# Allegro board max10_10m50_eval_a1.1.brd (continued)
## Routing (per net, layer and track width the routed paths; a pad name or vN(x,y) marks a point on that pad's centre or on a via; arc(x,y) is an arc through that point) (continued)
3.3V_EN: length 15
  ART04 w0.406: v2(23.62,67.56) 25.78,67.56 26.04,67.31 26.04,66.55 25.53,66.04 25.53,65.53 26.29,64.77 v2(26.29,64.01)
  BOTTOM w0.305: v2(23.62,67.56) 24.13,67.56 25.81,69.24 U17.18
  BOTTOM w0.406: v2(26.29,64.01) 26.29,64.77 26.8,65.28 C207.1 R284.2 R280.1 R279.1
3.3V_OV5640: length 1.3
  TOP w0.254: J3.16 55.19,12.26
  vias: v4(55.75,13.34) v4(55.75,12.45) v4(56.64,13.34) v4(56.64,12.45)
3.3V_POK: length 23.4
  TOP w0.147: v2(25.4,66.8) 25.4,66.29 25.15,66.04 25.15,64.39 26.67,62.86 28.24,62.86 28.38,62.72 R281.1 v2(29.34,62.23)
  BOTTOM w0.147: R282.2 33.59,55.56 34.29,56.26 34.29,61.09 33.66,61.72 29.84,61.72 v2(29.34,62.23) ; v2(25.4,66.8) 25.4,68.07 25.92,68.59 U17.17
3.3V_SI510: length 14.4
  ART04 w0.406: v2(35.56,56.13) 37.21,54.48 39.12,54.48 40.89,56.26 v2(44.2,56.26)
  BOTTOM w0.406: R214.1 35.43,56.26 v2(35.56,56.13) ; U15.6 41.79,55.56 C240.1 L9.2 v2(44.2,56.26)
3.3V_SI5338: length 5
  BOTTOM w0.254: U14.16 19.44,52.58 v2(19.18,52.32) ; U14.11 22.34,54.49 v2(22.48,54.36) ; v2(22.48,56.64) 22.33,56.49 U14.7 ; v2(20.19,52.32) 19.93,52.58 U14.15 ; U14.24 16.87,56.49 v2(16.76,56.39)
3.3V_VFB: length 4.9
  BOTTOM w0.305: R229.2 30.42,66.87 30.23,67.06 29.08,67.06 28.9,67.24 U17.14
  BOTTOM w0.406: R223.1 C91.2 R229.2
5V: length 21.7
  TOP w0.254: v2(86.61,60.58) 86.42,60.77 J4.18
  TOP w0.406: D2.8 74.97,65.06 v2(74.8,64.9) ; D1.8 74.88,60.62 v2(74.72,60.45)
  ART04 w0.617: J11.2 18.25,36.2 ; J11.2 17.14,37.3 ; J11.2 16.04,36.2 ; J11.2 17.14,35.09
  BOTTOM w0.406: v2(86.61,62.48) R115.2 R114.2 ; R280.2 28.13,61.4 ; R199.1 22.67,25.59 23.11,26.03 v4(23.11,28.32) ; C43.1 75.5,64.9 v2(74.8,64.9) ; C42.1 75.5,60.45 v2(74.72,60.45)
  BOTTOM w0.655: 16.14,36.2 J11.2 ; J11.2 17.14,37.2 ; J11.2 18.15,36.2
  vias: v4(16.64,37.72) v4(17.4,37.72) v4(20.19,74.17) v4(20.19,73.41) v4(21.08,74.17) v4(21.08,73.41) v4(21.97,74.17) v4(21.97,73.41) v4(23.11,30.1) v4(23.11,29.21) v4(23.88,30.1) v4(23.88,29.21) v4(23.88,28.32) v4(26.29,61.34) v4(26.29,60.58) v4(27.05,61.34) v4(27.05,60.58) v4(27.81,61.34) v4(27.81,60.58) v4(50.29,61.59) v4(50.29,60.71) v4(51.18,61.59) v4(51.18,60.71) v4(52.07,61.59) v4(52.07,60.71) v4(90.17,60.83) v4(90.17,59.94) v4(90.93,60.83) v4(90.93,59.94) v4(91.69,60.83) v4(91.69,59.94)
5V_DCIN: length 31.6
  TOP w0.254: V1.2 14.86,16.13 14.68,16.31 12.88,16.31 12.7,16.13 R222.2
  TOP w0.305: U18.2 25.53,15.56 25.65,15.68 R224.2
  TOP w0.406: R224.2 26.67,15.1 25.54,13.97 16.13,13.97 15.49,14.61 13.84,14.61
  TOP w0.508: R217.1 10.79,19.43 10.29,18.92 10.29,18.29
  TOP w0.762: J10.2 7.2,15.24 ; J10.2 9.26,15.24 ; J10.2 8.23,17.7 ; J10.2 8.23,12.78
5V_FB: length 3.4
  TOP w0.305: v2(20.57,17.27) 20.38,17.46 U18.12
  BOTTOM w0.406: R233.2 R226.1 v2(20.57,17.27)
5V_GATE: length 3.6
  TOP w0.254: U18.9 17.34,19.37 17.02,19.69 R225.2 R231.2
5V_IMON: length 2.5
  TOP w0.305: v2(17.27,16.76) 17.34,16.83 U18.13
  BOTTOM w0.406: R232.2 17.21,16.83 v2(17.27,16.76)
5V_LED_R: length 2
  TOP w0.406: v2(21.08,24.51) 21.26,24.33 D9.1
  BOTTOM w0.406: R199.2 v2(21.08,24.51)
5V_MONITOR: length 6.3
  TOP w0.305: 25.78,20.45 25.78,19.94 25.21,19.37 U18.8
  TOP w0.655: J11.1 20.69,36.2 ; J11.1 19.68,35.19 ; J11.1 19.68,37.2 ; J11.1 18.68,36.2
  vias: v4(21.84,21.97) v4(21.84,21.21) v4(22.61,21.97) v4(22.61,21.21) v4(23.37,21.97) v4(23.37,21.21) v4(24.13,21.97) v4(24.13,21.21)
5V_N: length 3.4
  TOP w0.254: V2.1 17.46,15.56 U18.15
5V_OV: length 3.6
  TOP w0.305: U18.4 25.91,16.83 26.16,16.57 R224.1
  TOP w0.406: R230.2 R224.1
5V_P: length 3.4
  TOP w0.254: V1.1 17.34,14.92 U18.16
5V_PG: length 2.8
  TOP w0.305: v2(17.27,18.54) 17.46,18.73 U18.10
  BOTTOM w0.406: R227.1 17.84,18.67 17.72,18.54 v2(17.27,18.54)
5V_R1.2CORE: length 17.8
  TOP w0.305: U21.16 18.12,25.52 18.35,25.29 C120.1
  TOP w0.406: C120.1 19.68,24.51 v2(20.45,25.27) 22.35,27.18 22.35,29.97 22.03,30.29 C111.1
  ART04 w0.508: v2(15.11,26.16) 15.37,25.91 19.81,25.91 v2(20.45,25.27)
  BOTTOM w0.406: v4(21.59,28.32) 21.91,28 R252.2
  vias: v4(20.07,29.21) v4(20.07,28.32) v4(20.83,29.21) v4(20.83,28.32) v4(21.59,29.21)
5V_R1.2VCCIO: length 6.6
  BOTTOM w0.203: U22.11 88.03,54.2 87.88,54.35 ; 88.43,53.59 U22.12
  BOTTOM w0.406: 87.88,54.35 87.69,54.54 C210.2 90.3,55.12 90.68,54.74 v4(90.68,54.36)
  vias: v4(89.15,54.36) v4(89.15,53.59) v4(89.92,54.36) v4(89.92,53.59) v4(90.68,53.59)
5V_R1.8: length 11.7
  TOP w0.406: v2(50.8,64.01) 50.8,64.64 51.05,64.9 R257.1
  BOTTOM w0.203: 53.34,62.74 53.98,62.74 54.23,62.99 54.23,63.75 54.17,63.81 U20.11 ; 53.34,61.98 54.36,61.98 54.97,62.59 U20.9 ; 52.83,63.63 53.21,63.63 53.38,63.79 U20.13 ; 53.34,62.36 54.1,62.36 54.57,62.83 U20.10
5V_R2.5: length 4.5
  TOP w0.203: C212.2 31.67,57.98 31.62,57.93 U19.11 ; U19.12 31.41,58.33
  TOP w0.406: v4(33.27,59.44) 32.89,59.05 32.89,58.17 32.7,57.98 C212.2
  vias: v4(31.75,60.32) v4(31.75,59.44) v4(32.51,60.32) v4(32.51,59.44) v4(33.27,60.32)
5V_R3.3: length 15.7
  ART04 w0.508: v4(26.29,65.79) 27.56,67.06 30.23,67.06 v4(30.99,67.82)
  BOTTOM w0.305: C96.1 27.24,66.8 27.6,67.16 U17.16
  BOTTOM w0.508: C96.1 26.8,66.29 v4(26.29,65.79) 25.65,65.15 23.24,65.15 22.86,65.53 22.86,68.96
5V_UV: length 21.4
  TOP w0.305: U18.3 22.54,16.19 v2(22.35,16.38) 20.64,18.1 U18.11
  BOTTOM w0.508: v2(22.35,16.38) 22.35,16 21.97,15.62 16.26,15.62 15.11,16.76 15.11,21.72 14.16,22.67 R264.2
GND: length 750.1
  TOP w0.152: U4.N3 U4.M4 ; U4.H18 U4.J17 ; U4.C8 U4.D9 ; U4.V13 U4.U12
  TOP w0.203: v2(28.19,56.26) 28.66,56.73 U19.5 ; v3(29.72,57.78) 29.57,57.93 U19.2 28.05,57.93 v2(27.81,58.17)
  TOP w0.254: J3.7 v2(50.68,12.31) ; v2(52.2,12.32) 52.19,12.31 J3.10 ; J3.3 48.68,12.11 v2(48.9,12.32) 49.19,12.03 J3.4
  TOP w0.305: J4.8 v2(86.69,65.77) ; U2.F5 v3(81.28,44.18) ; U4.U12 32.5,42.98 v3(32.77,43.24) ; U4.N18 U4.M18 U4.M17 34.49,44.97 33.91,44.39 v3(33.91,44.26) ; U4.H3 U4.J3 U4.J4 29.61,46.47 v3(30.11,45.97) ; U2.H2 v3(78.68,42.23) U2.J1 ; U18.7 22.42,18.73 v2(22.23,18.54) ; U4.D9 31,48.53 v3(30.48,48.01) ; v3(83.88,37.69) 83.64,37.92 U2.R9 ; v3(29.46,44.58) 29.07,44.97 U4.M4 ; J4.17 86.29,61.27 v2(86.61,61.59) ; J4.2 v2(86.69,68.77) ; U2.C2 v3(78.68,46.13) ; v3(84.8,40.61) U2.L10 ; C120.2 17.47,24.52 U21.15 ; U2.P1 v3(77.85,38.66) ; U2.N10 v3(84.8,39.31) ; U2.C6 v3(81.93,46.13) ; U2.P10 v3(84.8,38.66) ; U4.V8 U4.V9 U4.U9 31,42.85 v3(30.61,43.24) ; v3(32.89,48.07) 32.5,48.46 U4.D12 U4.C12 U4.C13 ; U2.M5 v3(80.63,39.64) ; U2.J8 v3(83.23,42.23) ; U2.E10 v3(83.88,44.18) ; U2.D10 v3(84.53,45.48) ; v3(78.03,45.48) U2.D1 ; J4.5 v2(86.69,67.27) ; U2.R6 v3(81.93,37.69) ; U2.R5 v3(80.63,37.69) ; v3(33.15,46.74) 34.04,46.74 v3(34.29,46.48) 34.3,46.47 U4.J17 ; U2.J5 v3(81.28,42.23) ; J4.11 v2(86.69,64.27) ; U2.G10 v3(83.88,42.88) ; U2.E1 v3(77.78,44.51) ; U2.C5 v3(81.28,46.13) ; U2.C9 v3(83.88,46.13) ; U2.N1 v3(77.85,39.31) ; U2.R2 v3(78.68,37.69)
  TOP w0.381: U1.E20 65.51,43.47 v1(65.51,43.46) ; U1.E20 64.52,43.47 v1(64.51,43.47) ; U1.E20 64.52,44.46 v1(64.52,44.47) ; U1.AA4 v1(48.51,28.46) ; v1(65.52,40.47) U1.J20 64.78,40.2 64.25,40.2 U1.J19 ; U1.T16 v1(61.52,32.46) ; U1.N4 v1(48.51,35.46) U1.P3 ; U1.P17 v1(62.52,35.47) ; U1.V6 v1(50.51,30.46) ; U1.M7 v1(51.51,36.46) ; U1.E17 62.51,43.47 v1(62.52,43.47) ; v1(50.51,43.47) U1.F6 ; U1.F6 50.52,42.47 v1(50.51,42.47) ; U1.F6 v1(51.51,43.47) ; U1.F20 65.51,42.47 v1(65.51,42.46) ; U1.F20 v1(64.51,42.46) ; U1.F20 v1(64.51,43.47) ; U1.F20 v1(65.51,43.46) ; U1.R19 v1(64.52,33.46) ; U1.D19 64.51,44.47 v1(64.52,44.47) ; U1.B21 v1(65.52,46.47) ; U1.B21 v1(66.52,47.47) ; U1.B21 65.52,47.46 v1(65.52,47.47) U1.B20 65.51,46.47 v1(65.52,46.47) ; v1(65.52,46.47) U1.C20 65.51,45.47 v1(65.51,45.46) ; U1.P2 47.02,34.96 v1(47.52,35.46) ; v1(65.51,43.46) 65.52,43.46 U1.F21 v1(65.51,42.46) ; U1.F19 64.51,43.46 v1(64.51,43.47) ; U1.F19 63.52,42.47 v1(63.51,42.47) ; U1.F19 64.51,42.47 v1(64.51,42.46) ; U1.Y12 v1(57.52,29.46) ; U1.V19 v1(63.52,30.46) ; U1.M22 v1(67.52,36.46) ; R20.1 v2(73.22,34.67) ; U1.E5 v1(49.51,44.47) ; U1.V2 v1(47.52,30.46) ; U1.N21 v1(66.52,36.46) U1.M21 ; U1.M16 v1(61.52,36.46) ; v1(64.52,44.47) U1.E19 v1(64.51,43.47) ; v1(64.52,44.47) U1.D20 v1(65.51,45.46) ; U1.D4 v1(48.51,45.47) ; U1.L13 v1(58.52,38.47) ; U1.L21 v1(66.52,38.47) ; v1(62.52,43.47) 62.52,43.46 U1.F18 ; v1(62.52,43.47) U1.F17 62.51,42.47 v1(62.52,42.47) ; U1.B13 v1(58.52,47.47) ; v1(65.51,45.46) U1.C21 v1(66.52,46.47) ; U1.B18 v1(63.52,47.47) ; U1.R22 v1(66.51,33.46) ; U1.B6 v1(50.51,47.47) ; U1.Y15 v1(59.51,29.47) ; v1(64.51,42.46) U1.G19 v1(63.51,42.47) ; v1(64.51,42.46) 64.52,42.46 U1.G20 ; U1.R3 v1(47.51,34.46) ; U1.G15 v1(60.52,42.47) ; U1.T4 v1(49.52,33.47) ; U1.U21 66.51,31.47 v1(66.52,31.47) ; v1(46.51,27.46) 46.01,26.97 U1.AB1 ; U1.V20 v1(65.52,30.46) ; v1(50.51,42.47) U1.G6 ; v1(50.51,42.47) U1.G5 ; U1.J16 v1(61.52,40.47) U1.H17 ; U1.D16 v1(61.52,45.47) ; U1.L22 v1(67.52,38.47) ; U1.AA18 v1(63.52,27.46) ; v1(65.51,42.46) 65.52,42.46 U1.G21 ; v1(62.52,42.47) U1.G17 ; v1(62.52,42.47) U1.F18 ; v1(62.52,42.47) 62.52,42.46 U1.G18 63.51,42.46 v1(63.51,42.47) ; U1.U13 v1(58.52,31.46) ; U1.W21 v1(65.52,29.46) ; U1.B9 v1(54.51,47.47) ; v1(67.52,31.47) 67.51,31.47 U1.U22 ; U1.F18 v1(63.51,42.47) ; U1.N13 v1(58.52,36.47) ; U1.V18 v1(62.51,31.47) ; U1.N15 v1(59.52,35.46) ; U1.T20 v1(65.52,32.46) ; U1.P6 v1(50.51,34.46) ; v1(50.51,32.46) 50.32,32.66 U1.T5 ; U1.T8 v1(52.51,33.46) ; U1.L17 v1(62.52,38.47) ; U1.P18 v1(63.52,34.46) ; U1.AB22 v1(66.51,27.47) ; U1.A1 v1(45.51,48.47) ; U1.A22 v1(67.52,48.47) ; U1.K12 v1(57.52,39.47) ; U1.F13 v1(58.52,43.47) ; U1.P19 v1(64.52,34.46) ; U1.N11 v1(55.51,35.46) ; U1.F10 v1(54.51,43.47) ; U1.E6 v1(50.51,44.47) ; U1.D11 v1(56.52,44.46) ; U1.T14 v1(59.51,32.47) ; C251.2 25.27,58.17 ; U1.Y9 v1(53.51,28.46) ; U1.M10 v1(54.51,36.46) ; v1(51.52,32.46) U1.T6 ; U1.P20 v1(65.52,34.46) ; U1.L19 v1(64.52,38.47) ; U1.E7 v1(51.51,44.47) ; U1.U10 v1(54.51,31.46) ; U1.M8 v1(52.51,36.46) ; U1.R21 v1(66.52,34.47) ; U1.M19 v1(64.52,36.46) ; U1.E2 v1(46.51,43.47)
  TOP w0.406: R144.1 41.34,45.85 41.4,45.91 C71.2 43.37,45.91 v2(43.43,45.97) ; 85.22,29.84 SW1.3 82.68,29.84 ; D9.2 19.05,23.24 18.92,23.37 v2(18.54,23.37) v2(17.78,23.37) v2(17.02,23.37) ; v1(39.62,36.45) 39.31,36.77 C122.2 ; 82.68,31.12 SW1.2 85.22,31.12 ; U1.J2 v1(47.51,39.47) ; v1(57.53,22.87) 57.48,22.92 C37.2 ; v2(73,14.63) S3.2 v2(69.87,14.63) S4.1 ; C120.2 v2(16.51,24.51) R243.1 ; v2(17.27,17.65) 17.02,17.91 C98.1 ; U1.K4 v1(48.52,39.47) ; U1.K5 v1(49.52,39.47) ; D2.7 76.4,65.71 v2(76.83,65.28) ; U1.J8 53.51,39.47 ; 53.51,39.47 U1.J9 v1(54.51,39.47) U1.K10 ; 53.51,39.47 v1(53.52,39.46) ; C212.1 32.96,57.09 v2(33.53,56.52) 33.53,55.75 33.2,55.42 D10.2 ; R230.1 27.69,15.11 v2(27.3,14.73) ; D1.7 74.87,61.27 v2(74.68,61.47) ; U1.K6 v1(50.52,39.47) U1.J6 v1(50.51,40.47) U1.H5 v1(49.51,40.47) U1.J5 ; U1.G8 v1(52.51,42.47) ; 85.22,28.58 SW1.4 v2(82.68,28.58) ; 85.22,32.38 SW1.1 82.68,32.38 ; C99.2 C97.2 28.32,17.65 v2(28.45,17.53) ; v1(70.74,29.59) 70.68,29.65 C31.2 ; U1.L5 v1(49.51,38.47) ; v1(78.74,33.02) 79.06,33.34 R180.1 ; 16.76,55.37 16.32,55.37 C88.2 ; R286.1 85.22,52.96 v2(85.09,53.09) ; v2(50.29,54.86) 50.29,54.61 v2(50.8,54.1) 50.86,54.04 C170.2 C169.1 ; U1.H11 v1(55.51,41.47) ; U1.K3 v1(47.51,38.47) ; S3.1 v2(76.83,14.63)
  TOP w0.508: SW2.4 39.5,55.24 ; C63.2 15.18,40.2 v2(15.24,40.26) ; SW2.2 39.5,57.78 ; SW2.1 39.5,59.05 ; J7.10 v2(10.16,46.35) ; SW2.3 39.5,56.52
  TOP w0.61: 61.34,6.44 J12.20 ; J12.20 62.52,7.62 ; J12.20 60.16,7.62 ; J12.20 61.34,8.8 ; 7,23.37 SW3.1 ; SW3.1 8,22.36 ; SW3.1 9,23.37 ; SW3.1 8,24.37 ; 1.91,27.44 SW3.6 ; SW3.6 1.91,29.45 ; SW3.6 2.91,28.45 ; 68.96,8.98 J12.13 ; J12.13 70.14,10.16 ; J12.13 68.96,11.34 ; J12.13 67.78,10.16 ; J4.G2 87.49,72.02 ; J4.G2 83.43,72.02 ; J4.G2 85.46,70.88 ; J4.G2 85.46,73.16 ; 60.16,10.16 J12.19 ; J12.19 61.34,8.98 ; J12.19 62.52,10.16 ; J12.19 61.34,11.34 ; 76.58,8.98 J12.7 ; J12.7 75.4,10.16 ; J12.7 77.76,10.16 ; J12.7 76.58,11.34 ; J12.8 77.76,7.62 ; J12.8 76.58,8.8 ; J12.8 76.58,6.44 ; J12.8 75.4,7.62 ; J12.14 70.14,7.62 ; J12.14 68.96,6.44 ; J12.14 67.78,7.62 ; J12.14 68.96,8.8 ; 85.46,56.38 J4.G4 ; J4.G4 83.43,57.52 ; J4.G4 85.46,58.66 ; J10.3 5.03,11.62 ; J10.3 5.03,9.46 ; J10.3 2.52,10.54 ; J10.3 7.55,10.54 ; J4.G1 91.43,73.16 ; J4.G1 89.68,72.02 ; J4.G1 91.43,70.88 ; J9.11 22.53,66.42 ; J9.11 20.65,66.42 ; J9.11 21.59,65.48 ; J5.5 8.46,34.6 ; J9.5 21.59,64.82 ; J9.5 21.59,62.94 ; J9.5 20.65,63.88 ; J9.5 22.53,63.88 ; J10.1 3.11,15.24 ; J10.1 2.03,17.75 ; J10.1 2.03,12.73
  GND02 w0.406: J14.12 72.06,73.66 ; J14.12 71.12,74.6 ; J14.12 70.18,73.66 ; J14.12 71.12,72.72 ; 2.03,12.93 J10.1 ; J10.1 2.91,15.24 ; J10.1 2.03,17.55 ; 75.7,10.16 J12.7 ; J12.7 77.46,10.16 ; J12.7 76.58,9.28 ; J12.7 76.58,11.04 ; J4.G2 87.29,72.02 ; J4.G2 85.46,71.08 ; J4.G2 83.63,72.02 ; J4.G2 85.46,72.96 ; J10.3 7.34,10.54 ; J10.3 2.72,10.54 ; J10.3 5.03,9.66 ; J10.3 5.03,11.42 ; J4.G4 85.46,58.46 ; J4.G4 83.63,57.52 ; J4.G4 85.46,56.58 ; J4.G4 87.29,57.52 ; 91.43,56.58 J4.G3 ; J4.G3 91.43,58.46 ; J4.G3 89.88,57.52 ; SW3.6 1.91,29.25 ; SW3.6 2.71,28.45 ; SW3.6 1.91,27.65 ; 75.7,7.62 J12.8 ; J12.8 76.58,6.74 ; J12.8 77.46,7.62 ; J12.8 76.58,8.5 ; 7.2,23.37 SW3.1 ; SW3.1 8,22.57 ; SW3.1 8,24.17 ; SW3.1 8.8,23.37 ; J8.11 44.45,67.36 ; J8.11 44.45,65.48 ; J8.11 43.51,66.42 ; J8.11 45.39,66.42 ; 8.19,34.6 J5.5 7.5,35.28 ; J13.14 26.29,8.5 ; J13.14 25.41,7.62 ; J13.14 27.17,7.62 ; J13.14 26.29,6.74 ; J12.19 62.22,10.16 ; J12.19 61.34,11.04 ; J12.19 61.34,9.28 ; J12.19 60.46,10.16 ; 18.67,7.62 18.67,8.5 ; 18.67,7.62 17.79,7.62 ; 18.67,7.62 18.67,6.74 ; 18.67,7.62 19.55,7.62 ; 25.41,10.16 J13.13 ; J13.13 27.17,10.16 ; J13.13 26.29,9.28 ; J13.13 26.29,11.04 ; J9.11 21.59,67.36 ; J9.11 21.59,65.48 ; J9.11 20.65,66.42 ; J9.11 22.53,66.42 ; J8.5 44.45,64.82 ; J8.5 44.45,62.94 ; J8.5 45.39,63.88 ; J8.5 43.51,63.88 ; J9.5 21.59,64.82 ; J9.5 21.59,62.94 ; J9.5 20.65,63.88 ; J9.5 22.53,63.88 ; 70.18,71.12 J14.11 ; J14.11 71.12,72.06 ; J14.11 72.06,71.12 ; J14.11 71.12,70.18 ; 61.34,6.74 J12.20 ; J12.20 61.34,8.5 ; J12.20 60.46,7.62 ; J12.20 62.22,7.62 ; 17.79,10.16 18.67,10.16 ; 18.67,10.16 18.67,11.04 ; 18.67,10.16 18.67,9.28 ; 18.67,10.16 19.55,10.16 ; 33.91,9.28 33.91,10.16 ; 33.91,10.16 33.03,10.16 ; 33.91,10.16 34.79,10.16 ; 33.91,10.16 33.91,11.04 ; 68.08,7.62 J12.14 ; J12.14 68.96,8.5 ; J12.14 68.96,6.74 ; J12.14 69.84,7.62 ; 33.91,7.62 34.79,7.62 ; 33.91,7.62 33.91,6.74 ; 33.91,7.62 33.03,7.62 ; 33.91,7.62 33.91,8.5 ; 68.08,10.16 J12.13 ; J12.13 68.96,9.28 ; J12.13 68.96,11.04 ; J12.13 69.84,10.16 ; 91.43,71.08 J4.G1 ; J4.G1 91.43,72.96 ; J4.G1 89.88,72.02
  GND05 w0.406: 2.03,12.93 J10.1 ; J10.1 2.91,15.24 ; J10.1 2.03,17.55 ; J10.3 7.34,10.54 ; J10.3 2.72,10.54 ; J10.3 5.03,9.66 ; J10.3 5.03,11.42 ; 18.67,7.62 18.67,8.5 ; 18.67,7.62 17.79,7.62 ; 18.67,7.62 18.67,6.74 ; 18.67,7.62 19.55,7.62 ; 68.96,6.74 J12.14 ; J12.14 68.96,8.5 ; J12.14 69.84,7.62 ; J12.14 68.08,7.62 ; 91.43,56.58 J4.G3 ; J4.G3 91.43,58.46 ; J4.G3 89.88,57.52 ; 20.65,66.42 J9.11 ; J9.11 22.53,66.42 ; J9.11 21.59,65.48 ; J9.11 21.59,67.36 ; J13.14 27.17,7.62 ; J13.14 25.41,7.62 ; J13.14 26.29,6.74 ; J13.14 26.29,8.5 ; 1.91,27.65 SW3.6 ; SW3.6 1.91,29.25 ; SW3.6 2.71,28.45 ; 71.12,72.72 J14.12 ; J14.12 70.18,73.66 ; J14.12 71.12,74.6 ; J14.12 72.06,73.66 ; 7.2,23.37 SW3.1 ; SW3.1 8,22.57 ; SW3.1 8,24.17 ; SW3.1 8.8,23.37 ; J9.5 22.53,63.88 ; J9.5 21.59,64.82 ; J9.5 20.65,63.88 ; J9.5 21.59,62.94 ; 91.43,71.08 J4.G1 ; J4.G1 91.43,72.96 ; J4.G1 89.88,72.02 ; 33.91,7.62 34.79,7.62 ; 33.91,7.62 33.03,7.62 ; 33.91,7.62 33.91,6.74 ; 33.91,7.62 33.91,8.5 ; J12.7 77.46,10.16 ; J12.7 76.58,11.04 ; J12.7 75.7,10.16 ; J12.7 76.58,9.28 ; J12.19 62.22,10.16 ; J12.19 60.46,10.16 ; J12.19 61.34,9.28 ; J12.19 61.34,11.04 ; 68.96,9.28 J12.13 ; J12.13 69.84,10.16 ; J12.13 68.96,11.04 ; J12.13 68.08,10.16 ; 43.51,63.88 J8.5 ; J8.5 44.45,62.94 ; J8.5 44.45,64.82 ; J8.5 45.39,63.88 ; 60.46,7.62 J12.20 ; J12.20 61.34,6.74 ; J12.20 61.34,8.5 ; J12.20 62.22,7.62 ; 26.29,9.28 J13.13 ; J13.13 26.29,11.04 ; J13.13 25.41,10.16 ; J13.13 27.17,10.16 ; 33.91,9.28 33.91,10.16 ; 33.91,10.16 34.79,10.16 ; 33.91,10.16 33.03,10.16 ; 33.91,10.16 33.91,11.04 ; J4.G2 87.29,72.02 ; J4.G2 85.46,71.08 ; J4.G2 83.63,72.02 ; J4.G2 85.46,72.96 ; 83.63,57.52 J4.G4 ; J4.G4 87.29,57.52 ; J4.G4 85.46,58.46 ; J4.G4 85.46,56.58 ; 18.67,9.28 18.67,10.16 ; 18.67,10.16 19.55,10.16 ; 18.67,10.16 18.67,11.04 ; 18.67,10.16 17.79,10.16 ; 43.51,66.42 J8.11 ; J8.11 44.45,65.48 ; J8.11 44.45,67.36 ; J8.11 45.39,66.42 ; 70.18,71.12 J14.11 ; J14.11 72.06,71.12 ; J14.11 71.12,70.18 ; J14.11 71.12,72.06 ; J12.8 76.58,8.5 ; J12.8 76.58,6.74 ; J12.8 77.46,7.62 ; J12.8 75.7,7.62 ; 7.5,35.28 J5.5 8.19,34.6
  BOTTOM w0.203: U22.5 86.83,51.02 v2(86.23,50.42) ; v2(55.88,67.18) 55.88,66.67 55.66,66.46 U20.6 ; v2(7.87,44.2) 8.26,43.81 U6.3 ; v1(87.88,51.94) 88.03,51.8 U22.2 88.03,50.53 v2(88.14,50.42) ; U20.3 53.78,67.24 ; U7.41 21.8,42.33 21.59,42.55 ; U20.2 53.38,67.27
  BOTTOM w0.254: v2(15.24,40.26) 15.8,40.82 U7.56 ; U7.6 16.89,44.33 ; v2(14.86,49.28) 14.86,48.46 14.99,48.33 U7.14 ; U7.28 22.3,49.6 v2(22.48,49.78) ; 19.44,56 U14.3 19.44,57.54 20,58.1 C89.1 ; U14.23 18.93,56 ; U7.53 17.3,42.93 ; U14.6 20.93,56.49 v5(20.57,56.13) ; U7.26 21.3,47.24 ; U7.10 16.89,46.33 ; U7.12 16.89,47.33 ; U14.4 19.93,56
  BOTTOM w0.305: v1(78.99,28.19) 79.04,28.15 J2.13 81.39,28.15 ; v1(32.13,26.67) 31.01,26.67 J1.21 ; R32.1 C10.2 80.8,46.13 v3(81.28,46.13) v3(81.93,46.13) ; C25.2 81.92,41.6 v3(81.28,42.23) 81.15,42.1 C17.2 ; J1.31 32.1,31.65 v1(32.13,31.62) ; v1(32.13,23.49) 31.98,23.65 J1.15 ; C11.2 84.11,43.12 v3(83.88,42.88) ; C16.2 81.93,37.92 v3(81.93,37.69) ; C73.2 v3(33.91,44.26) ; v3(78.68,42.23) 79.31,42.87 C23.2 ; C96.2 28.13,66.99 28.25,67.11 U17.15 ; v1(32.13,28.19) 32.7,28.19 32.74,28.15 J1.24 ; v1(78.99,29.72) 78.45,29.72 78.38,29.65 J2.10 76.09,29.65 ; v1(32.13,29.97) 31.81,29.65 J1.27 ; C72.2 v3(30.86,51.05) ; v3(83.88,44.18) 84.06,44.01 C245.2 ; v1(47.52,35.46) 47.04,35.94 46.29,35.94 45.97,36.26 C197.2 ; v1(78.99,24.89) 79.25,25.15 J2.19 81.39,25.15 ; v3(83.88,46.13) 83.63,45.88 83.63,45.47 C21.2 ; C19.2 78.29,44.01 v3(77.78,44.51) 77.52,44.77 C246.2 ; C15.2 84.96,40.45 v3(84.8,40.61) 84.65,40.77 R34.1 ; v1(32.13,25.15) 33.78,25.15 J1.18 ; v3(78.68,46.13) 78.8,46.26 C27.2 ; 76.09,26.65 J2.16 78.23,26.65 78.34,26.54 v1(78.99,26.54) ; C79.2 28.64,44.7 29.34,44.7 v3(29.46,44.58) ; R35.2 81.47,44.38 v3(81.28,44.18) ; C20.2 80.83,39.43 v3(80.63,39.64) ; v3(34.29,46.48) 34.73,46.93 C81.2 ; C246.2 77.09,45.59 ; C246.2 76.39,44.77 ; v3(32.89,48.07) 33.08,47.88 C76.2 ; v2(75.56,31.75) 75.67,31.65 J2.6 77.82,31.65 78.11,31.37 v1(78.99,31.37) 79.21,31.15 J2.7 ; v3(33.15,45.34) 33.08,45.28 C74.2 ; C22.2 83.63,41.84 v3(83.23,42.23) ; v1(78.99,23.24) 78.36,23.24 77.95,23.65 J2.22 76.09,23.65 ; C206.1 U1.G15 v1(60.52,42.47) ; C78.2 30.61,43.75 v3(30.61,43.24) 30.29,42.93 C80.2 ; C75.2 32.96,43.43 v3(32.77,43.24) 33.08,42.93 C77.2
  BOTTOM w0.381: C237.1 v1(61.52,32.46) 61.62,32.46 62.01,32.07 C148.1 ; C156.1 49.01,38.06 49.42,38.47 ; C233.1 63.01,41.97 v1(63.51,42.47) ; v1(53.52,39.46) 53.52,39.19 53.75,38.96 C238.1 ; U1.K4 49.01,38.87 49.41,38.47 49.42,38.47 ; C230.1 58.01,39.96 v1(57.52,39.47) U1.K12 C226.1 ; 49.42,38.47 v1(49.51,38.47) ; C223.2 51.27,40.47 v1(50.51,40.47) ; C239.1 v1(54.51,31.46) ; v1(62.52,35.47) 62.02,34.97 C149.1 ; C147.1 62.09,41.96 62.52,42.39 v1(62.52,42.47) ; v1(51.51,36.46) 51.51,36.54 51.09,36.96 C196.2 ; C124.1 52.01,33.87 52.42,33.46 v1(52.51,33.46) ; C228.1 54.01,36.07 54.41,36.46 v1(54.51,36.46) 55.04,36.99 C222.2 ; C236.1 62.01,38.87 62.41,38.47 v1(62.52,38.47) 62.73,38.25 C234.1 ; v1(58.52,36.47) 58.02,35.97 C229.1 C221.2 ; R18.1 58.1,38.05 v1(58.52,38.47) 58.61,38.47 59.01,38.87 C231.1 ; C235.1 v1(61.52,40.47) ; C225.1 v1(55.51,35.46) U1.N11 C224.1 ; C146.1 53.02,42.87 52.62,42.47 v1(52.51,42.47) ; U1.K10 v1(54.51,39.47) ; v1(58.52,31.46) 58.02,30.97 C144.1 ; v1(61.52,36.46) 61.41,36.46 61.01,36.07 C194.2 ; C145.1 v1(50.51,32.46)
  BOTTOM w0.406: v2(81.92,17.27) 81.04,18.15 J2.33 ; v2(76.83,65.28) 76.26,65.85 C43.2 ; R113.1 58.74,63.31 v2(58.8,63.37) ; v1(70.74,33.66) 70.68,33.59 C33.2 ; J1.3 32.13,17.65 32.63,18.15 J1.4 v2(35.19,18.15) ; R233.1 v2(21.46,16.38) ; v1(70.74,21.59) 70.68,21.65 C34.2 ; R11.1 C8.2 67.69,36.64 v1(67.52,36.46) ; 51.69,11.81 C38.2 50.68,10.66 50.67,10.67 ; C173.2 57.78,11.43 C39.2 ; v1(46.51,43.47) 46.48,43.5 R23.1 ; v2(17.27,17.65) 17.21,17.72 R232.1 16.51,19.18 ; v1(47.51,38.47) 47.21,38.16 C1.2 C3.2 R2.1 ; v2(33.53,56.52) 33.72,56.71 C175.2 ; v2(75.82,15.49) 75.97,15.65 J2.G3 ; C41.2 v1(54.8,22.92) ; J1.30 33.79,31.15 35.02,31.15 v2(35.56,30.61) ; J1.G1 32.41,15.65 v2(32.64,15.88) 32.86,15.65 J1.G4 34.95,15.65 v2(35.31,16) ; C210.1 85.47,55.12 v2(85.09,54.74) ; R112.1 R111.1 73.91,68.07 v2(74.17,68.33) ; C96.2 v2(28.83,66.29) R229.1 ; C40.2 58.86,22.92 v2(58.8,22.99) ; v2(82.55,26.54) C36.2 ; R124.2 10.03,34.67 v2(9.65,34.29) ; C35.2 70.68,26.99 v1(70.74,26.92) ; R8.1 60.66,30.61 v1(59.51,29.47) ; C207.2 R284.1 28.7,64.26 v2(28.83,64.39) ; C48.2 70.87,67.44 v2(71.12,67.69) ; C44.2 64.2,58.99 C45.2 ; J2.G2 v2(81.89,15.65) ; C32.2 70.68,24.32 v1(70.74,24.26) ; R22.1 v2(40.51,42.16) ; v2(76.07,17.14) 76.58,17.65 J2.34 ; R291.1 30.99,53.85 v2(30.73,53.59) ; J6.10 v2(5.71,56.52) ; R135.1 11.87,48.32 v2(12.45,48.89) ; C57.2 71.75,61.98 ; J1.8 34.84,20.15 v2(35.18,19.81) ; v2(35.05,25.15) 35.05,25.15 J1.18 ; C174.2 17.27,27.3
  BOTTOM w0.508: U23.10 53.59,59.69 v2(53.34,59.94) ; 25.03,7.62 J13.14 ; J13.14 27.55,7.62 ; J13.14 26.29,8.88 ; J13.14 26.29,6.36 ; U8.2 45.97,73.66 v2(45.85,73.79) ; 33.91,7.62 33.91,8.88 ; 33.91,7.62 32.65,7.62 ; 33.91,7.62 33.91,6.36 ; 33.91,7.62 35.17,7.62 ; 2.44,10.54 J10.3 ; J10.3 5.03,9.38 ; J10.3 5.03,11.7 ; J10.3 7.62,10.54 ; R221.1 8.7,22.67 SW3.1 ; v2(10.67,73.79) 10.41,73.53 U10.2 ; 33.91,10.16 35.17,10.16 ; 33.91,10.16 33.91,8.9 ; 33.91,10.16 32.65,10.16 ; 17.41,10.16 18.67,10.16 ; 18.67,10.16 18.67,11.42 ; 18.67,10.16 19.93,10.16 ; 18.67,10.16 18.67,8.9 ; R39.2 R52.2 R57.1 ; 2.03,12.65 J10.1 ; J10.1 2.03,17.83 ; J10.1 3.19,15.24 ; C28.2 35.05,24.9 v2(35.05,25.15) ; v2(86.61,61.59) 85.6,60.58 R117.2 ; 17.41,7.62 18.67,7.62 ; 18.67,7.62 19.93,7.62 ; 18.67,7.62 18.67,6.36 ; 18.67,7.62 18.67,8.88 ; v2(28.32,29.21) 28.32,30.48 C29.2 ; 25.03,10.16 J13.13 ; J13.13 26.29,8.9 ; J13.13 27.55,10.16 ; v2(81.66,19.94) 81.45,20.15 J2.29 ; 92.71,56.24 J4.G3 ; v2(17.14,68.45) 17.27,68.58 U11.2 ; U9.2 38.73,73.66 v2(38.61,73.79) ; v2(10.16,46.35) J7.10
  BOTTOM w0.61: J12.20 61.34,8.8 ; J12.20 62.52,7.62 ; J12.20 60.16,7.62 ; J12.20 61.34,6.44 ; J12.8 76.58,8.8 ; J12.8 75.4,7.62 ; J12.8 77.76,7.62 ; J12.8 76.58,6.44 ; J12.7 76.58,11.34 ; J12.7 77.76,10.16 ; J12.7 75.4,10.16 ; J12.7 76.58,8.98 ; 68.96,8.98 J12.13 ; J12.13 70.14,10.16 ; J12.13 67.78,10.16 ; J12.19 61.34,11.34 ; J12.19 62.52,10.16 ; J12.19 61.34,8.98 ; J12.19 60.16,10.16 ; 89.68,72.02 J4.G1 ; J4.G1 91.43,70.88 ; J4.G1 91.43,73.16 ; 67.78,7.62 J12.14 ; J12.14 70.14,7.62 ; J12.14 68.96,6.44 ; J12.14 68.96,8.8 ; 85.46,56.58 J4.G4 83.63,57.52 ; 85.46,70.88 J4.G2 ; J4.G2 83.43,72.02 ; J4.G2 85.46,73.16 ; J4.G2 87.49,72.02 ; J4.G3 91.43,58.66
  vias: v1(39.62,33.78) v1(39.62,31.12) v1(39.62,28.45) v1(39.62,25.78) v1(39.62,23.11) v1(43.43,23.24) v1(44.83,23.24) v1(45.39,25.91) v1(47.88,18.8) v1(49.02,16.38) v1(50.8,20.32) v1(52.07,20.32) v1(52.96,19.18) v1(55.5,19.18) v1(58.17,19.18) v1(60.83,19.18) v1(62.48,16.26) v1(63.75,16.26) v1(64.26,20.07) v1(64.52,16.26) v1(65.66,18.92) v1(66.29,16.89) v1(74.3,34.29) v1(74.3,31.62) v1(74.3,28.96) v1(74.3,26.29) v1(74.3,23.62) v1(74.3,20.95) v1(79.76,12.95) v1(80.39,11.81) v2(1.4,67.56) v2(1.52,20.32) v2(1.52,9.53) v2(1.52,6.6) v2(4.45,20.32) v2(5.08,6.6) v2(6.99,20.32) v2(7.62,74.3) v2(8.89,34.29) v2(8.89,33.02) v2(8.89,31.12) v2(9.53,20.32) v2(9.91,6.6) v2(10.29,40) v2(10.29,39.24) v2(11.05,44.2) v2(12.06,40.77) v2(12.57,44.32) v2(12.83,39.69) v2(12.95,40.77) v2(13.65,39.69) v2(15.24,61.59) v2(15.24,59.31) v2(16.64,59.94) v2(17.14,57.78) v2(17.78,20.07) v2(18.16,33.27) v2(18.54,20.07) v2(19.05,33.27) v2(19.3,20.07) v2(19.94,33.27) v2(20.32,60.83) v2(20.32,59.69) v2(20.57,13.21) v2(21.34,13.21) v2(21.59,59.69) v2(22.1,13.21) v2(22.86,13.21) v2(23.11,49.15) v2(23.62,13.21) v2(24.38,60.96) v2(25.4,46.35) v2(26.92,74.8) v2(27.18,22.61) v2(27.94,38.1) v2(27.94,22.61) v2(28.32,28.45) v2(28.32,27.56) v2(29.72,30.99) v2(29.72,30.23) v2(31.62,71.12) v2(31.62,70.36) v2(32.13,37.34) v2(33.15,38.1) v2(34.92,36.07) v2(35.05,39.88) v2(35.05,39.12) v2(35.31,34.29) v2(35.43,28.19) v2(35.56,60.32) v2(36.96,35.81) v2(36.96,32) v2(36.96,27.81) v2(37.08,29.34) v2(40.51,67.82) v2(41.15,17.02) v2(43.18,53.98) v2(43.43,44.96) v2(44.2,45.97) v2(44.2,44.96) v2(44.45,59.94) v2(44.83,11.81) v2(44.83,11.05) v2(45.72,11.81) v2(45.72,11.05) v2(46.35,19.56) v2(46.48,12.83) v2(46.61,11.81) v2(46.61,11.05) v2(48.26,9.53) v2(48.26,8.25) v2(50.16,9.53) v2(50.16,8.25) v2(53.34,59.05) v2(57.15,6.48) v2(58.8,65.91) v2(59.18,11.3) v2(59.18,10.41) v2(59.18,9.53) v2(59.18,8.64) v2(59.18,7.62) v2(59.31,66.42) v2(59.82,66.93) v2(60.07,11.3) v2(67.56,54.1) v2(67.82,51.94) v2(68.39,54.1) v2(68.58,51.94) v2(73.66,51.43) v2(74.42,57.28) v2(74.42,56.52) v2(75.44,55.63) v2(75.44,54.74) v2(75.56,58.8) v2(75.56,57.28) v2(75.56,28.58) v2(76.2,55.63) v2(76.2,54.74) v2(76.2,12.7) v2(77.34,12.19) v2(77.47,51.43) v2(78.23,12.19) v2(78.36,58.42) v2(78.36,56.9) v2(78.74,49.53) v2(78.74,35.15) v2(78.99,62.99) v2(79.38,59.69) v2(79.88,58.42) v2(80.64,59.69) v2(80.64,53.98) v2(80.64,51.43) v2(81.41,35.18) v2(81.66,49.28) v2(81.79,28.58) v2(81.79,27.81) v2(82.55,49.28) v2(82.68,27.81) v2(82.68,12.32) v2(83.57,74.68) v2(83.82,55.24) v2(85.72,33.15) v2(85.7,16.03) v2(85.85,6.48) v2(86.61,74.68) v2(86.59,16.03) v2(86.87,21.08) v2(87,38.73) v2(87,27.3) v2(88.27,69.85) v2(88.27,67.31) v2(88.27,19.05) v2(88.52,36.2) v2(88.9,50.42) v2(88.9,13.97) v2(89.28,43.81) v2(89.28,43.05) v2(89.53,38.73) v2(89.53,21.59) v2(89.53,14.61) v2(90.04,45.34) v2(90.04,44.58) v2(90.04,43.81) v2(90.04,43.05) v2(90.55,49.78) v2(90.55,49.02) v2(91.57,33.4) v2(92.46,74.68) v2(92.46,69.85) v2(92.46,65.41) v2(92.46,62.23) v2(92.58,46.35) v2(92.58,42.55) v2(92.58,38.73) v2(92.58,36.2) v2(92.58,33.4) v2(92.58,27.3) v2(92.61,22.63) v2(92.58,16.13) v2(92.58,13.97) v3(30.99,45.97) v4(2.03,44.58) v4(2.03,43.69) v4(2.92,44.58) v4(2.92,43.69) v4(3.81,44.58) v4(3.81,43.69) v4(10.67,27.81) v4(10.67,27.05) v4(11.56,27.81) v4(11.56,27.05) v4(12.45,27.81) v4(12.45,27.05) v4(23.75,74.55) v4(23.75,73.66) v4(23.75,58.42) v4(24.38,57.78) v4(24.64,74.55) v4(24.64,73.66) v4(24.77,58.42) v4(25.53,74.55) v4(25.53,73.66) v4(25.53,58.42) v4(32.64,69.6) v4(33.4,69.6) v4(34.16,69.6) v4(35.05,69.6) v4(50.8,68.83) v4(50.8,67.95) v4(51.56,68.83) v4(51.56,67.95) v4(52.32,68.83) v4(52.32,67.95) v5(16.26,28.96) v5(16.26,27.81) v5(16.64,47.5) v5(16.64,46.35) v5(16.64,45.09) v5(16.64,43.81) v5(16.64,42.8) v5(16.83,28.43) v5(16.83,27.28) v5(17.14,31.24) v5(17.14,29.72) v5(17.4,30.48) v5(17.4,28.96) v5(17.4,27.81) v5(17.78,47.5) v5(17.78,46.35) v5(17.78,45.09) v5(17.78,43.81) v5(17.78,42.8) v5(18.8,56.13) v5(18.8,55.24) v5(18.8,54.36) v5(19.05,47.5) v5(19.05,46.35) v5(19.05,45.09) v5(19.05,43.81) v5(19.05,42.8) v5(19.68,56.13) v5(19.68,55.24) v5(19.68,54.36) v5(20.32,47.5) v5(20.32,46.35) v5(20.32,45.09) v5(20.32,43.81) v5(20.32,42.8) v5(20.57,55.24) v5(20.57,54.36) v5(21.46,47.5) v5(21.46,46.35) v5(21.46,45.09) v5(21.46,43.81) v5(21.46,42.8) v5(28.32,72.16) v5(28.38,70.64) v5(28.38,69.49) v5(28.57,72.9) v5(28.7,71.48) v5(28.95,70.12) v5(28.96,68.96) v5(29.53,70.64) v5(29.53,69.49) v5(64.9,63.37) v5(64.9,62.23) v5(64.9,60.96) v5(64.9,59.82) v5(66.04,63.37) v5(66.04,62.23) v5(66.04,60.96) v5(66.04,59.82) v5(67.31,63.37) v5(67.31,62.23) v5(67.31,60.96) v5(67.31,59.82) v5(68.45,63.37) v5(68.45,62.23) v5(68.45,60.96) v5(68.45,59.82)
GND_EARTH: length 71.3
  TOP w0.554: J5.9 3.44,32.55 ; J5.9 1.95,31.55 ; J5.9 1.95,33.54 ; 6.6,31.55 J5.7 5.12,32.55 ; 1.95,38.85 J5.8 ; J5.8 3.44,39.84 ; J5.8 1.95,40.84 ; 5.12,39.84 J5.6 6.6,40.84
  GND02 w0.406: J5.8 3.44,39.84 ; J5.8 1.95,38.85 ; J5.8 1.95,40.84 ; 5.12,39.84 J5.6 6.6,40.84 ; 5.12,32.55 J5.7 6.6,31.55 ; J5.9 3.44,32.55 ; J5.9 1.95,33.54 ; J5.9 1.95,31.55
  VCC03 w0.406: 1.95,38.85 J5.8 ; J5.8 1.95,40.84 ; J5.8 3.44,39.84 ; J5.9 1.95,33.54 ; J5.9 3.44,32.55 ; J5.9 1.95,31.55 ; 6.6,31.55 J5.7 5.12,32.55 ; 6.6,40.84 J5.6 5.12,39.84
  ART04 w0.516: J5.8 3.44,39.84 ; J5.8 1.95,40.84 ; J5.8 1.95,38.85 ; J5.9 3.44,32.55 ; J5.9 1.95,31.55 ; J5.9 1.95,33.54 ; 5.12,39.84 J5.6 6.6,40.84 ; 5.12,32.55 J5.7 6.6,31.55
  GND05 w0.406: 1.95,31.55 J5.9 ; J5.9 1.95,33.54 ; J5.9 3.44,32.55 ; J5.8 1.95,40.84 ; J5.8 3.44,39.84 ; J5.8 1.95,38.85 ; 6.6,31.55 J5.7 5.12,32.55 ; 6.6,40.84 J5.6 5.12,39.84
  BOTTOM w0.554: 6.6,40.84 J5.6 5.12,39.84 ; J5.8 3.44,39.84 ; J5.8 1.95,40.84 ; J5.8 1.95,38.85 ; 5.12,32.55 J5.7 6.6,31.55 ; J5.9 1.95,33.54 ; J5.9 3.44,32.55 ; J5.9 1.95,31.55
  vias: v4(2.79,41.27) v4(3.68,41.27) v4(4.57,41.27) v4(5.46,41.27)
VBUS_5V: length 15.9
  TOP w0.406: 14.48,38.1 14.48,39.75 13.72,40.51 13.72,41.27 14.48,42.04 16.76,42.04 17.4,41.4 R133.1
  TOP w0.655: 14.61,35.19 J11.3 ; J11.3 14.61,37.2 ; J11.3 15.61,36.2 ; J11.3 13.6,36.2 ; 7.5,38.48 J5.1 8.25,37.79
  BOTTOM w0.655: 13.6,36.2 J11.3 14.61,35.19
24M_XTALIN: length 3.4
  BOTTOM w0.147: U7.5 14.17,43.84 13.7,43.37 C60.1 12.11,43.37 Y1.1
24M_XTALOUT: length 5.4
  BOTTOM w0.147: U7.4 14.12,43.33 13.73,42.94 13.73,42.75 C61.1 13.14,42.55 11.3,42.55 11.18,42.42 11.18,42.14 Y1.3
ADC_VREF: length 4.7
  TOP w0.381: U1.H6 v1(50.51,41.47)
  BOTTOM w0.305: R267.1 50.01,41.97 v1(50.51,41.47)
C_USB_MAX_TCK: length 35.1
  TOP w0.102: 26.16,41.22 27.24,41.22 27.49,41.47 U4.W2
  TOP w0.147: 26.16,41.22 25.51,41.22 25.15,41.58 v3(25.15,41.66)
  ART04 w0.109: v2(13.34,48.01) 13.59,48.26 15.11,48.26 16.13,49.28 22.1,49.28 23.37,48.01 23.37,46.61 23.62,46.35 24.51,46.35 26.04,44.83 26.04,42.55 v3(25.15,41.66)
  BOTTOM w0.147: J6.1 4.45,46.35 5.71,47.62 R135.2 10.99,47.17 11.17,46.99 12.32,46.99 v2(13.34,48.01) ; v3(25.15,41.66) 25.08,41.72 R129.1
C_USB_MAX_TDI: length 41
  TOP w0.102: U4.U2 27.25,42.22 26.47,42.22 v3(26.42,42.16)
  ART04 w0.109: v3(26.42,42.16) 25.4,41.15 24.89,41.15 24.64,41.4 24.64,42.71 24.98,43.05 24.98,44.49 24.38,45.09 23.37,45.09 22.35,46.1 22.35,47.88 21.84,48.39 16.26,48.39 15.11,47.24 14.1,47.24 13.84,46.99 12.95,46.99 11.94,48.01 11.94,49.15 11.3,49.78 11.3,50.42 10.92,50.8 10.92,51.69 10.79,51.82 v2(10.79,54.36)
  BOTTOM w0.147: R130.1 26.04,41.47 26.04,41.78 v3(26.42,42.16) ; J6.9 4.45,56.52 5.71,55.24 9.91,55.24 v2(10.79,54.36)
C_USB_MAX_TDO: length 38.9
  TOP w0.102: v3(26.42,41.66) 26.48,41.72 27.25,41.72 U4.V2
  ART04 w0.109: v3(26.42,41.66) 25.53,40.77 24.51,40.77 24.26,41.02 24.26,41.91 24,42.16 23.62,42.16 23.24,42.55 23.24,44.32 21.97,45.59 21.97,47.75 21.72,48.01 16.38,48.01 16,47.62 16,46.74 14.99,45.72 13.34,45.72 10.67,48.39 10.67,50.93 v2(10.41,51.18)
  BOTTOM w0.147: v2(10.41,51.18) 10.41,50.55 10.03,50.16 5.71,50.16 4.45,48.89 J6.3 ; v3(26.42,41.66) 26.48,41.59 R131.1
C_USB_MAX_TMS: length 38.5
  TOP w0.102: U4.T3 27.75,42.72 26.16,42.72
  TOP w0.147: v3(25.15,42.29) 25.58,42.72 26.16,42.72
  ART04 w0.109: v2(11.43,51.18) 11.94,50.67 11.94,49.78 12.19,49.53 12.57,49.53 12.95,49.15 12.95,48.64 12.7,48.39 12.7,47.75 12.95,47.5 13.59,47.5 13.84,47.75 15.11,47.75 16.13,48.77 22.1,48.77 22.73,48.13 22.73,46.48 23.5,45.72 24.38,45.72 25.65,44.45 25.65,42.8 v3(25.15,42.29)
  BOTTOM w0.147: J6.5 4.45,51.43 5.71,52.7 R136.2 10.99,51.63 v2(11.43,51.18) ; v3(25.15,42.29) 25.65,41.78 R132.1
CEC_CLK: length 2.5
  TOP w0.147: v2(73.91,65.91) 73.35,65.35 U3.32
  BOTTOM w0.147: R111.2 v2(73.91,65.91)
CEC_IO: length 3.9
  TOP w0.147: v2(73.91,64.9) 73.36,64.35 U3.30
  BOTTOM w0.147: v2(73.91,64.9) 74.53,65.52 74.53,66.22 R112.2
CLK24M: length 109.8
  TOP w0.147: U1.M9 v1(53.51,36.46)
  ART04 w0.109: v2(2.54,58.8) 3.17,58.17 3.17,46.74 6.35,43.56 7.11,43.56 9.27,41.4 9.27,37.21 13.84,32.64 13.84,25.65 14.73,24.77 15.75,24.77 16,25.02 16.73,25.02 17.12,24.64 19.05,24.64 20.45,23.24 22.86,23.24 23.37,23.75 24.89,23.75 25.65,22.99 25.65,21.21 26.29,20.57 33.4,20.57 33.91,21.08 35.43,21.08 36.07,20.45 37.59,20.45 40.13,22.99 40.13,30.73 46.28,36.88 53.1,36.88 v1(53.51,36.46)
  BOTTOM w0.147: v2(2.54,58.8) 3.05,59.31 4.45,59.31 4.7,59.05 13.72,59.05 15.05,57.72 R213.2
CLK24M_R: length 1.9
  BOTTOM w0.147: R213.1 16.76,55.75 17.02,55.49 U14.22
CLK50M_EN: length 1.9
  BOTTOM w0.147: U15.2 36,57.78 35.94,57.72 R214.2
CLK50M_MAX10: length 27.6
  TOP w0.147: U1.J10 v1(55.51,40.47)
  BOTTOM w0.147: R215.2 43.31,58.8 45.34,56.77 45.34,53.85 45.47,53.72 45.47,51.69 45.85,51.31 47.75,51.31 49.66,49.4 49.66,47.5 50.04,47.12 50.04,44.32 50.42,43.94 50.8,43.94 51.05,43.69 51.05,42.29 51.29,42.06 53.32,42.06 54.36,41.02 54.96,41.02 v1(55.51,40.47)
CLK50M_MAX10_R: length 1.9
  BOTTOM w0.147: R215.1 42.74,60.26 42.67,60.32 U15.4
CLK50M_MAXII: length 29.5
  TOP w0.147: U4.L1 v3(26.29,45.47)
  BOTTOM w0.147: R216.2 44.39,56.83 44.83,56.39 44.83,53.85 44.32,53.34 32.89,53.34 31.62,52.07 31.62,47.75 30.35,46.48 27.3,46.48 v3(26.29,45.47)
CLK50M_MAXII_R: length 1.9
  BOTTOM w0.147: R216.1 42.8,57.72 42.74,57.78 U15.5
CLK100M_LPDDR2: length 44.1
  TOP w0.147: U1.E10 v1(54.51,44.47)
  ART04 w0.109: v2(51.05,55.12) 50.67,55.5 49.53,55.5 48.64,54.61 42.04,54.61 40.01,52.58 31.5,52.58 30.61,51.69 27.81,51.69 v2(25.91,53.59)
  BOTTOM w0.147: v2(25.91,53.59) 24.96,53.59 R208.2 ; v2(51.05,55.12) 51.31,54.86 51.31,53.47 50.42,52.58 50.42,51.43 50.93,50.93 51.44,50.93 52.83,49.53 52.83,48.13 53.98,46.99 54.74,46.99 55.12,46.61 55.12,45.07 v1(54.51,44.47)
CLK100M_LPDDR2_BK: length 54.2
  ART04 w0.109: v2(26.92,53.59) 27.43,53.09 27.43,52.83 28.07,52.2 30.1,52.2 30.99,53.09 39.88,53.09 41.91,55.12 48.13,55.12 49.02,56.01 v2(51.05,56.01)
  BOTTOM w0.147: R17.2 61.01,37.71 61.01,42.62 60.67,42.97 57.36,42.97 56.01,44.32 56.01,47.62 54.1,49.53 54.1,50.16 52.07,52.2 52.07,54.99 v2(51.05,56.01) ; R207.2 25.34,54.1 26.42,54.1 v2(26.92,53.59)
CLK100M_LPDDR2_BK_R: length 2.1
  BOTTOM w0.147: U14.9 23.05,55.49 R207.1
CLK100M_LPDDR2_BKDIV: length 3.8
  TOP w0.147: U1.N14 v1(58.51,35.46)
  BOTTOM w0.147: v1(58.51,35.46) 58.99,35.94 R18.2 R17.1
CLK100M_LPDDR2_R: length 2.3
  BOTTOM w0.147: R208.1 22.67,55 U14.10
CLK125M: length 65.7
  TOP w0.147: v2(68.71,37.62) 68.71,36.83 70.1,35.43 R19.2
  ART04 w0.109: v2(51.05,57.15) 50.67,56.77 48.9,56.77 47.75,55.63 41.53,55.63 39.62,53.72 32.38,53.72 32,54.1 30.48,54.1 29.08,52.7 v2(28.45,52.7)
  BOTTOM w0.147: v2(28.45,52.7) 24.83,52.7 R210.2 ; v2(51.05,57.15) 52.32,57.15 53.59,55.88 53.59,52.32 57.02,48.89 57.02,44.26 57.31,43.97 63.35,43.97 64.01,43.3 64.01,38.09 64.49,37.62 v2(68.71,37.62)
CLK125M_DIV_R: length 1.8
  TOP w0.147: R270.1 R19.1 R20.2
CLK125M_R: length 3.4
  BOTTOM w0.147: U14.13 20.93,52.7 21.32,52.32 R210.1
CLKOUT_LVDS_N: length 40.5
  TOP w0.114: U1.W17 v1(62.52,29.46)
  ART04 w0.084: J12.18 64.73,7.62 65,7.89 65,13.1 63.75,14.35 59.4,14.35 58.93,14.83 58.93,15.65 59.4,16.13 61.09,16.13 61.34,16.38 61.34,16.89 61.09,17.14 59.4,17.14 58.89,17.66 58.89,18.25 59.31,18.67 64.48,18.67 64.86,19.04 64.86,19.22 v1(64.52,19.56)
  BOTTOM w0.114: v1(62.52,29.46) 62.83,29.78 63.13,29.78 63.56,29.34 63.56,28.17 64.99,26.74 64.99,24.54 R170.1 64.99,23.97 64.99,22.01 64.83,21.85 64.83,19.88 v1(64.52,19.56)
CLKOUT_LVDS_P: length 41.2
  TOP w0.114: U1.V17 v1(62.52,30.46)
  ART04 w0.084: J12.16 65.55,7.62 65.3,7.87 65.3,13.22 63.88,14.64 59.52,14.64 59.22,14.95 59.22,15.53 59.52,15.84 61.21,15.84 61.63,16.26 61.63,17.01 61.21,17.44 59.52,17.44 59.18,17.78 59.18,18.13 59.43,18.38 64.6,18.38 65.15,18.92 65.15,19.3 v1(65.41,19.56)
  BOTTOM w0.114: v1(62.52,30.46) 62.88,30.1 63.26,30.1 63.88,29.48 63.88,28.3 65.31,26.87 65.31,26.26 65.53,26.03 65.53,25.69 65.31,25.47 65.31,24.54 R170.2 65.31,23.97 65.31,21.88 65.15,21.72 65.15,19.81 v1(65.41,19.56)
EXT_JTAG_TCK: length 41.3
  TOP w0.147: R148.2 12.83,57.78 13.46,58.42 22.61,58.42 24.51,56.52 24.51,54.1 26.67,51.94 36.58,51.94 37.72,50.8 37.72,48.13 38.1,47.75 39.18,47.75 R143.1 R144.2 38.61,45.85 37.59,44.83 36.64,44.83 U4.M20
EXT_JTAG_TCK_R: length 9
  TOP w0.147: R148.1 5.71,57.78 4.45,56.52 2.48,56.52
EXT_JTAG_TDI: length 30.5
  TOP w0.147: v3(34.04,47.31) 34.66,47.31 U4.H17 ; R152.2 R146.1 12.45,48.01 13.34,48.89 v2(13.34,50.16)
  ART04 w0.109: v3(34.04,47.31) 33.78,47.31 33.46,47.62 30.23,47.62 29.97,47.88 29.97,48.51 29.59,48.89 28.45,48.89 27.69,48.13 25.91,48.13 24.64,49.4 24.64,49.66 21.46,52.83 17.53,52.83 15.11,50.42 13.59,50.42 v2(13.34,50.16)
EXT_JTAG_TDI_R: length 9.3
  TOP w0.147: R152.1 10.29,46.99 9.65,47.62 5.71,47.62 4.45,46.35 J7.9
EXT_JTAG_TDO: length 30.8
  TOP w0.147: R149.2 v2(12.7,54.42) ; v3(34.04,48.07) 34.62,48.07 34.72,47.97 U4.F17
  ART04 w0.109: v3(34.04,48.07) 33.08,49.02 30.86,49.02 29.97,49.91 28.19,49.91 27.43,49.15 26.16,49.15 25.53,49.78 25.53,50.04 21.84,53.72 17.02,53.72 15.81,52.51 14.92,52.51 13.97,51.56 12.95,51.56 12.06,52.45 12.06,53.78 v2(12.7,54.42)
EXT_JTAG_TDO_R: length 9
  TOP w0.147: 2.48,53.98 4.57,53.98 5.84,55.24 R149.1
EXT_JTAG_TMS: length 29
  TOP w0.147: R145.1 R150.2 11.87,51.63 v2(12.32,51.18) ; U4.G17 34.78,47.69 v3(34.42,47.69)
  ART04 w0.109: v2(12.32,51.18) 12.57,50.93 14.99,50.93 17.4,53.34 21.59,53.34 25.02,49.91 25.02,49.66 26.04,48.64 27.56,48.64 28.32,49.4 29.72,49.4 30.61,48.51 33.02,48.51 33.85,47.69 v3(34.42,47.69)
EXT_JTAG_TMS_R: length 9.4
  TOP w0.147: J7.5 4.45,51.43 5.71,52.7 9.65,52.7 10.41,51.94 R150.1
FLASH_CLK: length 6.8
  TOP w0.147: v2(54.1,52.58) 54.1,48.73 54.01,48.64 U1.A9
  BOTTOM w0.147: U23.16 54.61,52.07 v2(54.1,52.58)
FLASH_CSN: length 16.5
  TOP w0.147: U1.A8 53.01,56.46 50.61,58.86 R245.2 v2(49.28,59.69)
  BOTTOM w0.147: U23.7 v2(49.28,59.69)
FLASH_D0: length 9.9
  TOP w0.147: v2(54.1,53.47) 53.51,52.88 53.51,46.47 U1.C9
  BOTTOM w0.147: U23.15 54.23,53.34 v2(54.1,53.47)
FLASH_D1: length 20.7
  TOP w0.147: U1.C10 v1(54.51,46.47)
  BOTTOM w0.147: U23.8 48.9,60.96 49.91,59.94 49.91,55.5 49.66,55.24 49.66,54.74 49.85,54.55 49.85,51.12 50.8,50.16 51.31,50.16 52.2,49.28 52.2,47.75 53.48,46.47 v1(54.51,46.47)
FLASH_D2: length 23
  TOP w0.147: U1.C11 v1(56.52,45.46)
  BOTTOM w0.147: v1(56.52,45.46) 56.52,48.13 54.86,49.78 54.86,50.29 52.83,52.32 52.83,55.37 51.69,56.52 50.8,56.52 50.55,56.77 50.55,58.04 53.47,60.96 U23.9
FLASH_D3: length 7.8
  TOP w0.147: U1.A7 52.01,49.59 50.16,51.43 v2(49.15,51.43)
  BOTTOM w0.147: v2(49.15,51.43) 48.51,52.07 U23.1
FLASH_RESETN: length 26.1
  TOP w0.147: R250.1 R244.2 v2(49.28,54.23)
  ART04 w0.109: v2(49.28,54.23) 48.51,53.47 41.53,53.47 40.13,52.07 32.64,52.07 v3(32,51.43)
  BOTTOM w0.147: R249.1 32.19,51.24 v3(32,51.43) ; U23.3 48.9,54.61 v2(49.28,54.23)
FLASH_RESETN_MAX10: length 11.6
  TOP w0.147: R250.2 51.5,56.58 52.51,55.56 52.51,47.47 U1.B8
FLASH_RESETN_MAXII: length 6.6
  TOP w0.147: v3(33.53,43.31) 33.53,42.8 33.5,42.77 U4.U14
  BOTTOM w0.147: v3(33.53,43.31) 33.53,45.97 33.66,46.1 33.66,48.2 R249.2
FX2_D_N: length 16.7
  BOTTOM w0.147: J5.2 8.05,37 8.79,37.74 8.79,41.26 8.03,42.02 8.03,42.63 U6.2 8.33,43.18 8.53,43.18 11.11,45.76 14.44,45.76 14.51,45.84 U7.9
FX2_D_P: length 15.5
  BOTTOM w0.147: U7.8 14.51,45.33 14.44,45.41 11.26,45.41 U6.1 8.38,42.53 8.38,42.16 9.14,41.4 9.14,37.59 8.2,36.64 7.95,36.64 J5.3
FX2_FLAGA: length 7.4
  TOP w0.147: U4.H4 29.06,46.97 v3(29.08,46.99)
  BOTTOM w0.147: v3(29.08,46.99) 25.91,46.99 24.38,48.51 23.75,48.51 23.57,48.33 U7.29
FX2_FLAGB: length 4.4
  TOP w0.147: v2(23.88,47.88) 25.4,47.88 26.1,47.18 26.79,47.18 U4.H1
  BOTTOM w0.147: U7.30 23.83,47.84 v2(23.88,47.88)
FX2_FLAGC: length 4.4
  TOP w0.147: v2(24.64,47.37) 25.4,47.37 26.04,46.74 26.73,46.74 U4.J1
  BOTTOM w0.147: v2(24.64,47.37) 23.59,47.37 23.56,47.33 U7.31
FX2_PA0: length 9.1
  TOP w0.147: v3(29.72,44.07) 29.34,44.07 28.94,44.47 U4.N4
  BOTTOM w0.147: U7.33 24.66,46.33 26.92,44.07 v3(29.72,44.07)
FX2_PA1: length 7.7
  TOP w0.147: U4.P4 28.8,43.97 v3(29.08,43.69)
  BOTTOM w0.147: v3(29.08,43.69) 26.8,43.69 24.65,45.84 U7.34
FX2_PA2: length 8.9
  TOP w0.147: v3(29.72,43.31) 28.96,43.31 28.8,43.47 U4.R4
  BOTTOM w0.147: v3(29.72,43.31) 26.67,43.31 24.64,45.33 U7.35
FX2_PA3: length 7.5
  TOP w0.147: v3(29.08,42.93) 28.54,42.93 U4.T4
  BOTTOM w0.147: U7.36 24.63,44.84 26.54,42.93 v3(29.08,42.93)
FX2_PA4: length 4.3
  TOP w0.147: v2(24.38,44.32) 25.03,44.97 U4.M1
  BOTTOM w0.147: v2(24.38,44.32) 23.9,44.32 23.89,44.33 U7.37
FX2_PA5: length 4.3
  TOP w0.147: v2(23.75,43.81) 24.64,43.81 25.29,44.47 U4.N1
  BOTTOM w0.147: U7.38 23.73,43.84 v2(23.75,43.81)
FX2_PA6: length 4.3
  TOP w0.147: v2(24.38,43.31) 24.86,43.31 25.53,43.97 U4.P1
  BOTTOM w0.147: v2(24.38,43.31) 23.9,43.31 23.88,43.33 U7.39
FX2_PA7: length 4.3
  TOP w0.147: U4.R1 25.56,43.47 24.89,42.8 v2(23.75,42.8)
  BOTTOM w0.147: U7.40 23.71,42.84 v2(23.75,42.8)
FX2_PB0: length 12.9
  TOP w0.147: U4.D1 26.34,48.97 23.88,51.43 17.71,51.43 17.3,51.03 v2(17.3,50.55)
  BOTTOM w0.147: U7.18 v2(17.3,50.55)
FX2_PB1: length 12.2
  TOP w0.147: U4.E1 26.35,48.47 23.76,51.05 18.08,51.05 17.8,50.77 v2(17.8,49.91)
  BOTTOM w0.147: U7.19 v2(17.8,49.91)
FX2_PB2: length 11.4
  TOP w0.147: U4.F1 26.33,47.97 23.62,50.67 18.91,50.67 18.78,50.55 v2(18.3,50.55)
  BOTTOM w0.147: U7.20 v2(18.3,50.55)
FX2_PB3: length 10.5
  TOP w0.147: U4.G1 26.32,47.47 23.5,50.29 19.18,50.29 v2(18.8,49.91)
  BOTTOM w0.147: U7.21 v2(18.8,49.91)
FX2_PB4: length 13.5
  TOP w0.147: v3(29.08,48.51) 28.96,48.51 U4.D4
  BOTTOM w0.147: v3(29.08,48.51) 26.51,48.51 23.59,51.43 20.57,51.43 19.3,50.16 U7.22
FX2_PB5: length 13.4
  TOP w0.147: v3(29.46,48.13) 28.84,48.13 U4.E4
  BOTTOM w0.147: v3(29.46,48.13) 26.35,48.13 23.43,51.05 20.83,51.05 19.8,50.03 U7.23
FX2_PB6: length 11.9
  TOP w0.147: U4.F4 28.72,47.75 v3(29.08,47.75)
  BOTTOM w0.147: U7.24 20.3,49.89 21.08,50.67 23.27,50.67 26.19,47.75 v3(29.08,47.75)
FX2_PB7: length 11.9
  TOP w0.147: U4.G4 28.78,47.47 28.88,47.37 v3(29.46,47.37)
  BOTTOM w0.147: v3(29.46,47.37) 26.04,47.37 23.11,50.29 21.34,50.29 20.8,49.76 U7.25
FX2_PD0: length 4.6
  BOTTOM w0.147: U7.45 21.3,40.3 21.59,40 22.73,40 22.74,40.01 22.76,40.01 23.59,40.83 R129.2
FX2_PD1: length 6.4
  BOTTOM w0.147: R132.2 25.34,40.07 25.15,40.26 23.62,40.26 22.99,39.62 21.34,39.62 20.8,40.16 U7.46
FX2_PD2: length 8.5
  BOTTOM w0.147: U7.47 20.3,39.9 20.95,39.24 23.24,39.24 23.88,39.88 24.89,39.88 25.27,39.5 25.97,39.5 R130.2
FX2_PD3: length 11
  BOTTOM w0.147: U7.48 19.8,39.64 20.57,38.86 23.37,38.86 24,39.5 24.77,39.5 25.12,39.14 26.57,39.14 27.43,40 R131.2
FX2_PD4: length 12.1
  TOP w0.147: v1(24.89,38.73) 26.04,39.88 26.91,39.88 U4.Y3
  BOTTOM w0.147: U7.49 19.3,39.5 20.32,38.48 23.56,38.48 24.09,39.01 24.62,39.01 v1(24.89,38.73)
FX2_PD5: length 13
  TOP w0.147: v1(24.26,38.61) 24.26,38.99 25.65,40.39 26.92,40.39 U4.Y2
  BOTTOM w0.147: U7.50 18.8,39.24 19.94,38.1 21.21,38.1 21.46,37.85 23.88,37.85 24.26,38.23 v1(24.26,38.61)
FX2_PD6: length 14.6
  TOP w0.147: U4.Y4 26.9,39.37 26.16,39.37 v1(25.53,38.73)
  BOTTOM w0.147: v1(25.53,38.73) 24.13,37.34 21.34,37.34 20.95,37.72 19.56,37.72 18.3,38.98 U7.51
FX2_PD7: length 16.2
  TOP w0.147: U4.Y5 26.76,38.73 v1(26.16,38.73)
  BOTTOM w0.147: U7.52 17.8,38.71 19.18,37.34 20.83,37.34 21.34,36.83 24.26,36.83 v1(26.16,38.73)
FX2_RESETN: length 14.4
  TOP w0.147: v3(32.45,40.39) 32.75,40.39 33,40.64 U4.Y13
  ART04 w0.109: v3(32.45,40.39) 31.81,39.75 29.21,39.75 28.57,40.39 24.13,40.39 23.75,40.77 v2(23.75,41.4)
  BOTTOM w0.147: v3(32.45,40.39) R126.1 32.25,39.17 U5.2 ; U7.42 23.57,41.84 23.75,41.66 v2(23.75,41.4)
FX2_SCL: length 25.8
  TOP w0.147: U4.B1 26.61,49.97 v3(26.42,50.16)
  ART04 w0.109: v3(26.42,50.16) 26.42,50.93 23.5,53.85 23.5,54.36 21.84,56.01 21.84,56.77 21.46,57.15 18.41,57.15 16.89,55.63 16.89,55.37 16.26,54.74 16.26,54.1 15.24,53.09 15.04,53.09 14.02,52.07 v2(13.34,52.07)
  BOTTOM w0.147: R127.2 v3(26.42,50.16) ; U7.15 15.8,49.6 15.37,50.04 14.48,50.04 13.34,51.18 v2(13.34,52.07)
FX2_SDA: length 29.3
  ART04 w0.109: v3(28.19,51.05) 27.69,51.05 24.77,53.98 24.77,55.88 22.23,58.42 16.89,58.42 15.37,56.9 15.37,54.86 14.35,53.85 14.35,53.59 v2(13.97,53.21)
  BOTTOM w0.147: v2(13.97,53.21) 13.97,51.43 14.61,50.8 15.49,50.8 16.3,49.99 U7.16 ; R123.1 R128.2 28,50.86 v3(28.19,51.05)
FX2_SLRDN: length 18.3
  TOP w0.147: U4.Y6 26.63,38.1 23.37,38.1 20.83,40.64 17.27,40.64 16.64,41.27 v2(14.99,41.27)
  BOTTOM w0.147: U7.1 14.75,41.84 14.61,41.69 14.61,41.54 14.87,41.27 v2(14.99,41.27)
FX2_SLWRN: length 20.8
  TOP w0.147: U4.Y7 26.75,37.72 23.11,37.72 20.57,40.26 16.89,40.26 16.38,40.77 v2(14.35,40.77)
  BOTTOM w0.147: v2(14.35,40.77) 13.97,41.15 13.97,41.66 14.65,42.33 U7.2
FX2_WAKEUP: length 4.5
  TOP w0.406: v3(21.84,40.39) 21.72,40.51 C62.1 R134.2 20.51,41.4 R133.2
  BOTTOM w0.254: U7.44 21.8,40.43 v3(21.84,40.39)
HDMI_DDCSCL: length 18.6
  TOP w0.147: U3.33 70.43,66.53 70.67,66.29 70.87,66.29 72.01,67.44 74.68,67.44 75.1,67.02 D2.5 76.75,67.02 v2(77.6,66.17) ; J4.15 83.27,62.27 v2(83.06,62.48)
  BOTTOM w0.147: R115.1 v2(83.06,62.48) 81.28,62.48 v2(77.6,66.17)
HDMI_DDCSDA: length 19.4
  TOP w0.147: U3.34 69.92,66.35 70.48,65.79 71.25,65.79 72.26,66.8 74.3,66.8 74.73,66.37 D2.6 76.64,66.37 v2(76.83,66.17) ; v2(83.06,61.59) 83.23,61.77 J4.16
  BOTTOM w0.147: v2(76.83,66.17) 81.41,61.59 v2(83.06,61.59) R114.1
HDMI_HPD: length 23.7
  TOP w0.147: D1.5 76.62,62.57 v2(76.83,62.36) ; J4.19 83.37,60.27 v2(83.06,60.58) ; v2(76.2,56.52) 75.31,56.52 74.04,55.24 70.61,55.24 70.43,55.43 U3.16
  BOTTOM w0.147: R117.1 v2(83.06,60.58) 80.14,60.58 78.36,62.36 v2(76.83,62.36) 76.83,57.15 v2(76.2,56.52)
HDMI_HSYNC: length 30.4
  TOP w0.147: U1.H13 v1(58.52,41.47) ; U3.64 60.21,57.84 59.9,57.53 59.9,57.36 v2(59.56,57.02)
  ART04 w0.109: v1(58.52,41.47) 58.14,41.84 58.14,43.84 58.04,43.94 57.28,43.94 57.02,44.2 57.02,45.85 56.64,46.23 56.64,47.12 57.06,47.54 57.06,57.32 57.28,57.53 58.68,57.53 58.8,57.41 58.8,57.14 58.68,57.02 57.65,57.02 57.53,56.91 57.53,56.63 57.65,56.52 58.68,56.52 58.8,56.4 58.8,56.12 58.68,56.01 57.65,56.01 57.53,55.89 57.53,55.62 57.65,55.5 59.45,55.5 59.56,55.62 v2(59.56,57.02)
HDMI_INTR: length 25.5
  TOP w0.147: v2(70.87,62.99) 71.22,63.35 U3.28 ; U1.A18 v1(62.59,48.39)
  ART04 w0.109: v2(70.87,62.99) 71.37,62.48 71.37,57.53 70.36,56.52 69.33,56.52 69.22,56.4 69.22,55.36 69.1,55.24 68.7,55.24 68.58,55.36 68.58,56.4 68.46,56.52 68.06,56.52 67.94,56.4 67.94,55.27 62.23,49.56 62.23,48.75 v1(62.59,48.39)
  BOTTOM w0.147: R122.1 70.42,62.93 70.48,62.99 v2(70.87,62.99)
HDMI_IREF: length 2.6
  TOP w0.254: U3.14 69.43,54.44 69.28,54.29 R116.2
HDMI_SCL: length 30.7
  TOP w0.147: U1.C16 v1(61.52,46.47) ; U3.35 69.43,66.19 69.58,66.04 69.58,65.39 v2(68.96,64.77)
  ART04 w0.109: v1(61.52,46.47) 61.52,47.37 61.09,47.8 61.09,49.63 66.67,55.22 66.67,57.66 67.31,58.29 69.09,58.29 69.85,59.05 69.85,64.26 69.66,64.45 69.28,64.45 v2(68.96,64.77)
  BOTTOM w0.147: R121.1 68.45,67.12 68.45,65.28 v2(68.96,64.77)
HDMI_SDA: length 26.9
  TOP w0.147: U1.B17 v1(62.44,47.39) ; U3.36 68.92,65.82 v2(68.96,65.79)
  ART04 w0.109: v1(62.44,47.39) 61.72,48.1 61.72,49.66 67.18,55.12 67.18,57.53 67.44,57.78 69.22,57.78 70.36,58.93 70.36,64.39 v2(68.96,65.79)
  BOTTOM w0.147: R120.1 68.96,66.61 v2(68.96,65.79)
HDMI_VIDEO_CLK: length 30
  TOP w0.147: U1.D6 51.51,45.46 v1(51.51,45.47) ; v2(58.8,62.51) 59.64,63.35 U3.53
  ART04 w0.109: v2(58.8,62.51) 57.81,63.5 56.38,63.5 56.26,63.38 56.26,63.11 56.38,62.99 57.54,62.99 57.66,62.88 57.66,62.6 57.54,62.48 55.63,62.48 53.85,60.71 53.85,58.42 53.59,58.17 53.59,50.29 51.31,48.01 51.31,45.67 v1(51.51,45.47)
  BOTTOM w0.147: R113.2 58.71,62.42 v2(58.8,62.51)
HDMI_VIDEO_DATA_EN: length 31.7
  TOP w0.147: U1.J13 v1(58.52,40.47) ; v2(59.56,58.04) 59.87,58.35 U3.63
  ART04 w0.109: v1(58.52,40.47) 57.89,41.09 57.89,41.53 56.13,43.29 56.13,47.37 56.64,47.88 56.64,59.95 56.76,60.07 57.67,60.07 57.78,59.95 57.78,59.68 57.67,59.56 57.26,59.56 57.14,59.45 57.14,59.17 57.26,59.05 58.56,59.05 58.67,58.94 58.67,58.66 58.56,58.55 57.27,58.55 57.15,58.43 57.15,58.16 57.27,58.04 v2(59.56,58.04)
HDMI_VIDEO_DIN0: length 31.1
  TOP w0.147: v2(59.56,58.84) U3.62 ; U1.J12 v1(57.52,40.47)
  ART04 w0.109: v1(57.52,40.47) 57.52,41.29 55.9,42.91 55.9,47.1 55.75,47.24 55.24,47.24 55.12,47.37 55.12,47.88 55.24,48.01 56.26,48.01 56.39,48.13 56.39,48.39 56.26,48.51 55.88,48.51 55.75,48.64 55.75,48.89 56.13,49.28 56.13,60.2 56.52,60.58 58.94,60.58 59.05,60.46 59.05,60.19 58.94,60.07 58.41,60.07 58.29,59.95 58.29,59.68 58.41,59.56 58.84,59.56 v2(59.56,58.84)
HDMI_VIDEO_DIN1: length 29.1
  TOP w0.147: U3.61 61.89,59.35 v2(62.36,59.82) ; U1.D13 v1(58.52,45.47)
  ART04 w0.109: v1(58.52,45.47) 58.52,45.84 59.05,46.38 59.05,48.51 58.46,49.11 58.46,49.46 58.93,49.93 58.93,50.16 58.46,50.63 58.46,51.69 58.59,51.82 59.57,51.82 59.69,51.7 59.69,51.42 59.57,51.31 59.04,51.31 58.93,51.19 58.93,50.92 59.04,50.8 59.69,50.8 60.33,51.43 60.33,52.07 60.58,52.32 61.22,52.32 61.85,52.95 61.85,54.36 61.21,54.99 61.21,60.58 61.34,60.71 61.59,60.71 61.72,60.58 61.72,58.42 61.85,58.29 62.23,58.29 62.36,58.42 v2(62.36,59.82)
HDMI_VIDEO_DIN2: length 28.8
  TOP w0.147: U1.E12 v1(57.52,44.47) ; v2(59.56,59.84) U3.60
  BOTTOM w0.147: v1(57.52,44.47) 58.01,44.96 58.01,46.71 58.27,46.97 58.71,46.97 59.56,47.82 59.56,49.28 58.8,50.04 58.8,53.45 58.95,53.59 59.16,53.59 59.31,53.45 59.31,50.31 59.46,50.16 59.67,50.16 59.82,50.31 59.82,53.72 58.8,54.74 58.8,55.5 58.95,55.65 59.47,55.65 59.62,55.8 59.62,56.09 59.47,56.24 58.95,56.24 58.8,56.39 58.8,59.55 59.1,59.84 v2(59.56,59.84)
HDMI_VIDEO_DIN3: length 29.1
  TOP w0.147: U1.E13 v1(58.52,44.47) ; U3.59 62.12,60.35 v2(62.36,60.58)
  ART04 w0.109: v2(62.36,60.58) 61.85,61.09 61.85,61.47 61.72,61.59 61.34,61.59 60.71,60.96 60.71,54.23 60.83,54.1 61.22,54.1 61.34,53.99 61.34,53.58 61.22,53.47 58.16,53.47 58.04,53.35 58.04,53.08 58.16,52.96 60.08,52.96 60.2,52.84 60.2,52.57 60.08,52.45 58.16,52.45 58.04,52.33 58.04,44.94 v1(58.52,44.47)
